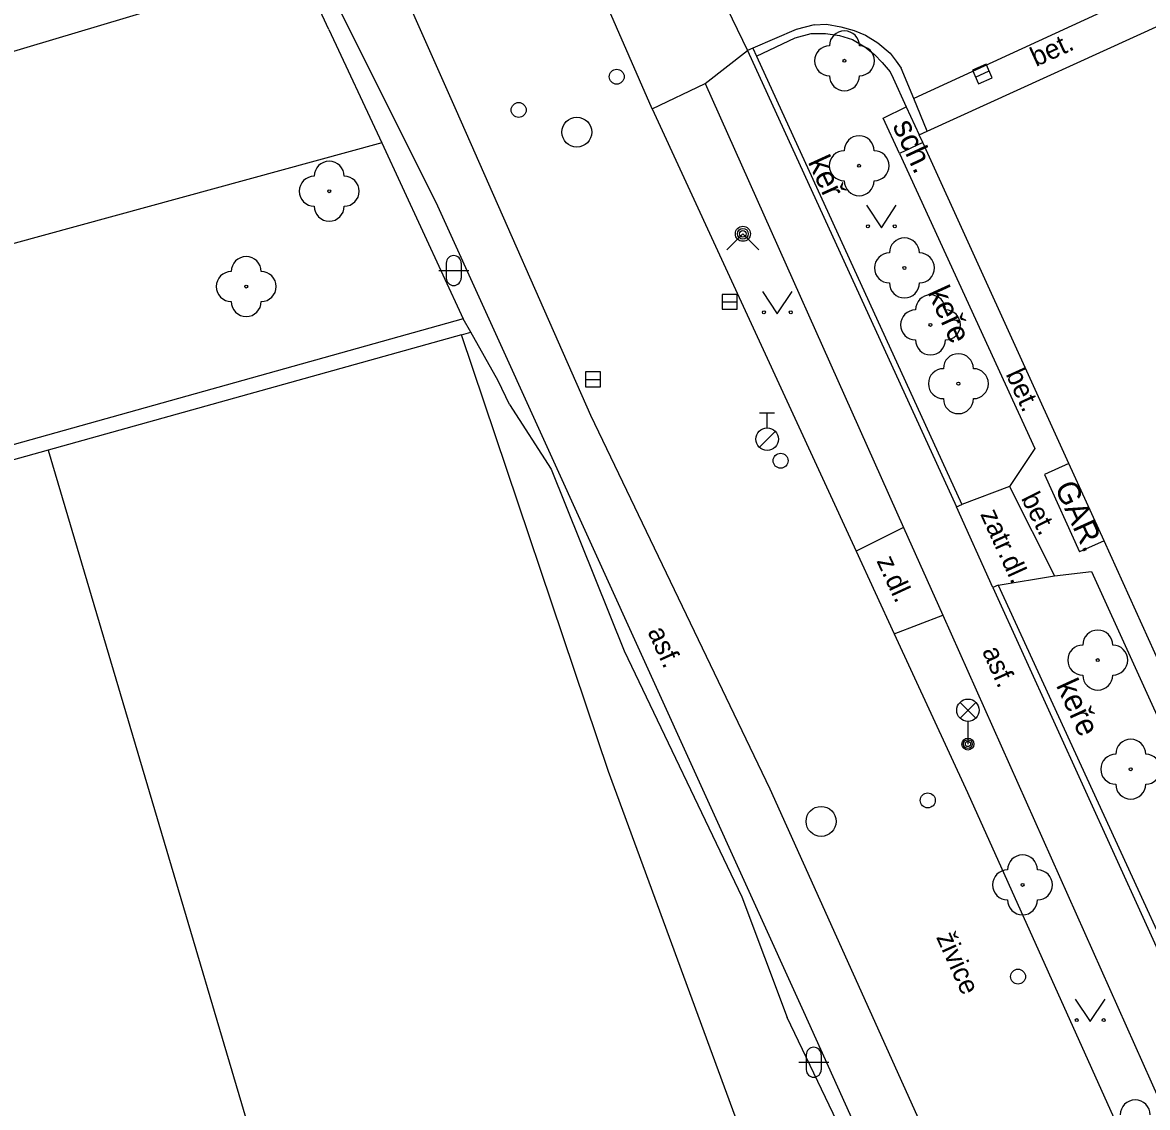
# Model space of a CAD drawing. Extents: x -595546 to -593986, y -1160845 to -1159202.
# Drawn here: x -595396.28 to -595358.75, y -1160329.89 to -1160293.7 of the extents above; entities that cross this region are included whole.
import ezdxf

# ---------------------------------------------------------------- set-up
doc = ezdxf.new("R2010")
doc.units = 0
for name, color, linetype in [('Level 22', 7, 'Continuous'), ('Level 27', 7, 'Continuous'), ('Level 28', 7, 'Continuous'), ('Level 31', 7, 'Continuous'), ('Level 33', 7, 'Continuous'), ('Level 36', 7, 'Continuous'), ('Specificka linie pasportu komunikaci', 7, 'Continuous'), ('TM - budovy zdene_ betonove - VP', 7, 'Continuous'), ('TM - chodniky - VP', 7, 'Continuous'), ('TM - komunikace - VP', 7, 'Continuous'), ('TM - letecke snimky - pomocna linie', 7, 'Continuous'), ('TM - plot drateny_ kovovy - VP', 7, 'Continuous'), ('TM - podezdivka plotu - VP', 7, 'Continuous'), ('TM - popis objektu', 7, 'Continuous'), ('TM - popis povrchu', 7, 'Continuous'), ('TM - popis zelene', 7, 'Continuous'), ('TM - poznamka', 7, 'Continuous'), ('TM - rozhrani mezi zpev. plochami mezi sebou - VP', 7, 'Continuous'), ('TM - rozhrani ploch obecne - VP', 7, 'Continuous'), ('TM - vjezd na pozemek', 7, 'Continuous'), ('TM - zed operna - VP', 7, 'Continuous')]:
    doc.layers.add(name, color=color, linetype=linetype)

msp = doc.modelspace()

# ---------------------------------------------------------------- linework, layer by layer
at = {"layer": 'Level 22'}
for centre in [(-595368.86, -1160294.98), (-595368.37, -1160298.48), (-595386.05, -1160299.33), (-595366.86, -1160301.89), (-595388.82, -1160302.51), (-595365.99, -1160303.79), (-595365.06, -1160305.75), (-595360.41, -1160314.97), (-595359.31, -1160318.61), (-595362.92, -1160322.47)]:
    msp.add_circle(centre, 0.05, dxfattribs=at)
for centre, start, end in [((-595368.86, -1160294.48), 0, 180), ((-595369.36, -1160294.98), 90, 270), ((-595368.36, -1160294.98), 270, 90), ((-595368.86, -1160295.48), 180, 0), ((-595368.37, -1160297.98), 0, 180), ((-595368.87, -1160298.48), 90, 270), ((-595367.87, -1160298.48), 270, 90), ((-595386.05, -1160298.83), 0, 180), ((-595386.55, -1160299.33), 90, 270), ((-595385.55, -1160299.33), 270, 90), ((-595368.37, -1160298.98), 180, 0), ((-595386.05, -1160299.83), 180, 0), ((-595366.86, -1160301.39), 0, 180), ((-595367.36, -1160301.89), 90, 270), ((-595366.36, -1160301.89), 270, 90), ((-595388.82, -1160302.01), 0, 180), ((-595389.32, -1160302.51), 90, 270), ((-595388.32, -1160302.51), 270, 90), ((-595366.86, -1160302.39), 180, 0), ((-595365.99, -1160303.29), 0, 180), ((-595388.82, -1160303.01), 180, 0), ((-595366.49, -1160303.79), 90, 270), ((-595365.49, -1160303.79), 270, 90), ((-595365.99, -1160304.29), 180, 0), ((-595365.06, -1160305.25), 0, 180), ((-595365.56, -1160305.75), 90, 270), ((-595364.56, -1160305.75), 270, 90), ((-595365.06, -1160306.25), 180, 0), ((-595360.41, -1160314.47), 0, 180), ((-595360.91, -1160314.97), 90, 270), ((-595359.91, -1160314.97), 270, 90), ((-595360.41, -1160315.47), 180, 0), ((-595359.31, -1160318.11), 0, 180), ((-595359.81, -1160318.61), 90, 270), ((-595358.81, -1160318.61), 270, 90), ((-595359.31, -1160319.11), 180, 0), ((-595362.92, -1160321.97), 0, 180), ((-595363.42, -1160322.47), 90, 270), ((-595362.42, -1160322.47), 270, 90), ((-595362.92, -1160322.97), 180, 0), ((-595359.16, -1160330.14), 0, 180)]:
    msp.add_arc(centre, 0.5, start, end, dxfattribs=at)
at = {"layer": 'Level 27'}
for p, q in [((-595364.488, -1160295.523), (-595364.032, -1160295.317)), ((-595372.94, -1160303.02), (-595372.44, -1160303.02)), ((-595377.5, -1160305.61), (-595377, -1160305.61))]:
    msp.add_line(p, q, dxfattribs=at)
for points in [[(-595364.385, -1160295.751), (-595363.929, -1160295.545), (-595364.135, -1160295.089), (-595364.591, -1160295.295)], [(-595372.94, -1160303.27), (-595372.44, -1160303.27), (-595372.44, -1160302.77), (-595372.94, -1160302.77)], [(-595377.5, -1160305.86), (-595377, -1160305.86), (-595377, -1160305.36), (-595377.5, -1160305.36)]]:
    msp.add_lwpolyline(points, close=True, dxfattribs=at)
for centre in [(-595377.79, -1160297.36), (-595369.64, -1160320.35)]:
    msp.add_circle(centre, 0.5, dxfattribs=at)
at = {"layer": 'Level 28'}
for p, q in [((-595371.69, -1160306.725), (-595371.19, -1160306.725)), ((-595371.44, -1160307.225), (-595371.44, -1160306.725)), ((-595371.698, -1160307.872), (-595371.168, -1160307.342))]:
    msp.add_line(p, q, dxfattribs=at)
for centre, radius in [((-595376.46, -1160295.51), 0.25), ((-595379.73, -1160296.62), 0.25), ((-595371.44, -1160307.6), 0.375), ((-595370.99, -1160308.32), 0.25), ((-595366.08, -1160319.65), 0.25), ((-595363.07, -1160325.53), 0.25)]:
    msp.add_circle(centre, radius, dxfattribs=at)
at = {"layer": 'Level 31'}
msp.add_lwpolyline([(-595372.78, -1160301.28), (-595372.25, -1160300.75), (-595371.72, -1160301.28)], dxfattribs=at)
for radius in [0.25, 0.18, 0.11]:
    msp.add_circle((-595372.25, -1160300.75), radius, dxfattribs=at)
at = {"layer": 'Level 33'}
for p, q in [((-595365.005, -1160316.91), (-595364.475, -1160316.38)), ((-595365.005, -1160316.38), (-595364.475, -1160316.91)), ((-595364.74, -1160317.02), (-595364.74, -1160317.77))]:
    msp.add_line(p, q, dxfattribs=at)
for centre, radius in [((-595364.74, -1160316.645), 0.375), ((-595364.74, -1160317.77), 0.2), ((-595364.74, -1160317.77), 0.145), ((-595364.74, -1160317.77), 0.0876)]:
    msp.add_circle(centre, radius, dxfattribs=at)
at = {"layer": 'Level 36'}
for p, q in [((-595382.146, -1160301.726), (-595382.146, -1160302.226)), ((-595381.646, -1160301.726), (-595381.646, -1160302.226)), ((-595382.396, -1160301.976), (-595381.396, -1160301.976)), ((-595370.386, -1160328.386), (-595369.386, -1160328.386)), ((-595370.136, -1160328.136), (-595370.136, -1160328.636)), ((-595369.636, -1160328.136), (-595369.636, -1160328.636))]:
    msp.add_line(p, q, dxfattribs=at)
for points in [[(-595368.13, -1160299.8), (-595367.63, -1160300.55), (-595367.13, -1160299.8)], [(-595371.6, -1160302.67), (-595371.1, -1160303.42), (-595370.6, -1160302.67)], [(-595361.16, -1160326.28), (-595360.66, -1160327.03), (-595360.16, -1160326.28)]]:
    msp.add_lwpolyline(points, dxfattribs=at)
for centre in [(-595368.08, -1160300.5), (-595367.181, -1160300.5), (-595371.55, -1160303.37), (-595370.651, -1160303.37), (-595361.11, -1160326.98), (-595360.211, -1160326.98)]:
    msp.add_circle(centre, 0.05, dxfattribs=at)
for centre, start, end in [((-595381.896, -1160301.726), 0, 180), ((-595381.896, -1160302.226), 180, 0), ((-595369.886, -1160328.136), 0, 180), ((-595369.886, -1160328.636), 180, 0)]:
    msp.add_arc(centre, 0.25, start, end, dxfattribs=at)
at = {"layer": 'Specificka linie pasportu komunikaci'}
msp.add_lwpolyline([(-595387.05, -1160291.81), (-595399.46, -1160295.52)], dxfattribs=at)
at = {"layer": 'TM - budovy zdene_ betonove - VP'}
for points in [[(-595366.1, -1160297.33), (-595357.22, -1160293.28)], [(-595366.37, -1160297.45), (-595366.1, -1160297.33)], [(-595366.25, -1160297.71), (-595366.37, -1160297.45)], [(-595361.38, -1160308.41), (-595366.25, -1160297.71)], [(-595361.38, -1160308.41), (-595362.19, -1160308.78)], [(-595360.2, -1160310.99), (-595361.38, -1160308.41)], [(-595362.19, -1160308.78), (-595361.02, -1160311.36)], [(-595360.2, -1160310.99), (-595361.02, -1160311.36)], [(-595358.29, -1160315.19), (-595360.2, -1160310.99)]]:
    msp.add_lwpolyline(points, dxfattribs=at)
at = {"layer": 'TM - chodniky - VP'}
for points in [[(-595388.83, -1160287.65), (-595388.56, -1160287.57), (-595383.63, -1160297.43)], [(-595375.28, -1160296.58), (-595373.51, -1160295.74)], [(-595373.51, -1160295.74), (-595366.89, -1160310.55)], [(-595383.63, -1160297.43), (-595382.44, -1160299.82), (-595370.23, -1160326.69), (-595365.18, -1160337.88), (-595363.98, -1160340.95)], [(-595366.89, -1160310.55), (-595368.47, -1160311.34)], [(-595367.2, -1160314.1), (-595365.58, -1160313.47)], [(-595365.58, -1160313.47), (-595356.4, -1160334.02), (-595354.14, -1160339.07)]]:
    msp.add_lwpolyline(points, dxfattribs=at)
at = {"layer": 'TM - komunikace - VP'}
for points in [[(-595386.32, -1160286.47), (-595384.65, -1160290.24), (-595381.82, -1160296.64)], [(-595375.28, -1160296.58), (-595377.23, -1160292.09)], [(-595381.82, -1160296.64), (-595377.33, -1160306.8), (-595371.35, -1160319.27), (-595363.57, -1160336.54), (-595361.97, -1160340.09)], [(-595375.28, -1160296.58), (-595368.47, -1160311.34)], [(-595368.47, -1160311.34), (-595367.2, -1160314.1)], [(-595367.2, -1160314.1), (-595364.76, -1160319.39), (-595357.93, -1160334.56), (-595355.6, -1160339.73)]]:
    msp.add_lwpolyline(points, dxfattribs=at)
at = {"layer": 'TM - letecke snimky - pomocna linie'}
for points in [[(-595381.64, -1160304.12), (-595381.33, -1160304.03)], [(-595395.43, -1160307.97), (-595384.96, -1160343.33)]]:
    msp.add_lwpolyline(points, dxfattribs=at)
at = {"layer": 'TM - plot drateny_ kovovy - VP'}
for points in [[(-595386.06, -1160293.93), (-595384.3, -1160297.72)], [(-595371.79, -1160294.83), (-595370.5, -1160294.21)], [(-595370.5, -1160294.21), (-595369.97, -1160294.07), (-595369.49, -1160294.07), (-595369.03, -1160294.14), (-595368.59, -1160294.27), (-595368.18, -1160294.51), (-595367.86, -1160294.77), (-595367.6, -1160295.04), (-595367.34, -1160295.35), (-595367.24, -1160295.56)], [(-595371.92, -1160294.56), (-595371.79, -1160294.83)], [(-595371.79, -1160294.83), (-595364.94, -1160309.78)], [(-595367.24, -1160295.56), (-595366.8, -1160296.51)], [(-595366.8, -1160296.51), (-595366.37, -1160297.45)], [(-595384.3, -1160297.72), (-595381.58, -1160303.59)], [(-595381.58, -1160303.59), (-595401.7, -1160309.21)], [(-595381.33, -1160304.03), (-595381.58, -1160303.59)], [(-595380.41, -1160305.66), (-595381.33, -1160304.03)], [(-595380.04, -1160306.45), (-595378.65, -1160308.6), (-595376.21, -1160314.66)], [(-595363.73, -1160312.47), (-595353.53, -1160334.67)], [(-595376.21, -1160314.66), (-595372.28, -1160322.87), (-595370.77, -1160326.89)], [(-595365.67, -1160337.55), (-595370.77, -1160326.89)]]:
    msp.add_lwpolyline(points, dxfattribs=at)
at = {"layer": 'TM - podezdivka plotu - VP'}
for points in [[(-595369.87, -1160293.78), (-595370.47, -1160293.94), (-595371.92, -1160294.56)], [(-595371.92, -1160294.56), (-595372.1, -1160294.64)], [(-595372.1, -1160294.64), (-595365.12, -1160309.86)], [(-595366.55, -1160296.24), (-595366.97, -1160295.22)], [(-595366.1, -1160297.33), (-595366.55, -1160296.24)], [(-595365.12, -1160309.86), (-595364.94, -1160309.78)], [(-595363.73, -1160312.47), (-595363.91, -1160312.55)], [(-595363.91, -1160312.55), (-595353.79, -1160334.79)]]:
    msp.add_lwpolyline(points, dxfattribs=at)
at = {"layer": 'TM - rozhrani mezi zpev. plochami mezi sebou - VP'}
for points in [[(-595357.67, -1160292.15), (-595366.55, -1160296.24)], [(-595373.51, -1160295.74), (-595372.1, -1160294.64)], [(-595363.35, -1160309.18), (-595361.85, -1160312.16)], [(-595366.89, -1160310.55), (-595365.58, -1160313.47)]]:
    msp.add_lwpolyline(points, dxfattribs=at)
at = {"layer": 'TM - rozhrani ploch obecne - VP'}
for points in [[(-595369.87, -1160293.78), (-595369.46, -1160293.76), (-595368.98, -1160293.85), (-595368.54, -1160293.97), (-595368.16, -1160294.12), (-595367.75, -1160294.38), (-595367.34, -1160294.72), (-595367.14, -1160294.99), (-595366.97, -1160295.22)], [(-595367.02, -1160298.07), (-595367.57, -1160296.89), (-595366.8, -1160296.51)], [(-595384.3, -1160297.72), (-595403.37, -1160302.93)], [(-595366.25, -1160297.71), (-595367.02, -1160298.07)], [(-595367.02, -1160298.07), (-595362.51, -1160307.91)], [(-595381.64, -1160304.12), (-595395.43, -1160307.97)], [(-595369.39, -1160338.66), (-595376.73, -1160318.69), (-595381.64, -1160304.12)], [(-595395.43, -1160307.97), (-595426.68, -1160316.68)], [(-595360.62, -1160312.02), (-595350.86, -1160333.45)]]:
    msp.add_lwpolyline(points, dxfattribs=at)
at = {"layer": 'TM - vjezd na pozemek'}
for points in [[(-595373.99, -1160290.72), (-595372.1, -1160294.64)], [(-595386.06, -1160293.93), (-595386.51, -1160292.98)], [(-595380.04, -1160306.45), (-595380.41, -1160305.66)], [(-595363.91, -1160312.55), (-595365.12, -1160309.86)]]:
    msp.add_lwpolyline(points, dxfattribs=at)
at = {"layer": 'TM - zed operna - VP'}
for points in [[(-595362.51, -1160307.91), (-595363.35, -1160309.18)], [(-595363.35, -1160309.18), (-595364.94, -1160309.78)], [(-595363.73, -1160312.47), (-595361.85, -1160312.16)], [(-595361.85, -1160312.16), (-595360.62, -1160312.02)]]:
    msp.add_lwpolyline(points, dxfattribs=at)

# ---------------------------------------------------------------- texts
at = {"layer": 'TM - popis objektu'}
msp.add_text('GAR.', height=0.75, rotation=294.4877, dxfattribs=at).set_placement((-595361.86, -1160309.2))
at = {"layer": 'TM - popis povrchu'}
for s, rotation, p in [('bet.', 24.6769, (-595362.47, -1160295.19)), ('bet.', 294.4877, (-595363.49, -1160305.43)), ('bet.', 296.7187, (-595362.98, -1160309.57)), ('zatr.dl.', 294.5045, (-595364.34, -1160310.1)), ('z.dl.', 294.7592, (-595367.8, -1160311.66)), ('asf.', 294.4375, (-595375.44, -1160314.02)), ('asf.', 294.0832, (-595364.28, -1160314.67)), ('živice', 294.2387, (-595365.81, -1160324.21))]:
    msp.add_text(s, height=0.65, rotation=rotation, dxfattribs=at).set_placement(p)
at = {"layer": 'TM - popis zelene'}
for s, rotation, p in [('keř', 294.3864, (-595370.09, -1160298.35)), ('keře', 294.5335, (-595366.1, -1160302.7)), ('keře', 294.5335, (-595361.81, -1160315.81))]:
    msp.add_text(s, height=0.75, rotation=rotation, dxfattribs=at).set_placement(p)
at = {"layer": 'TM - poznamka'}
msp.add_text('sch.', height=0.75, rotation=294.9903, dxfattribs=at).set_placement((-595367.27, -1160297.14))

doc.saveas('drawing.dxf')
